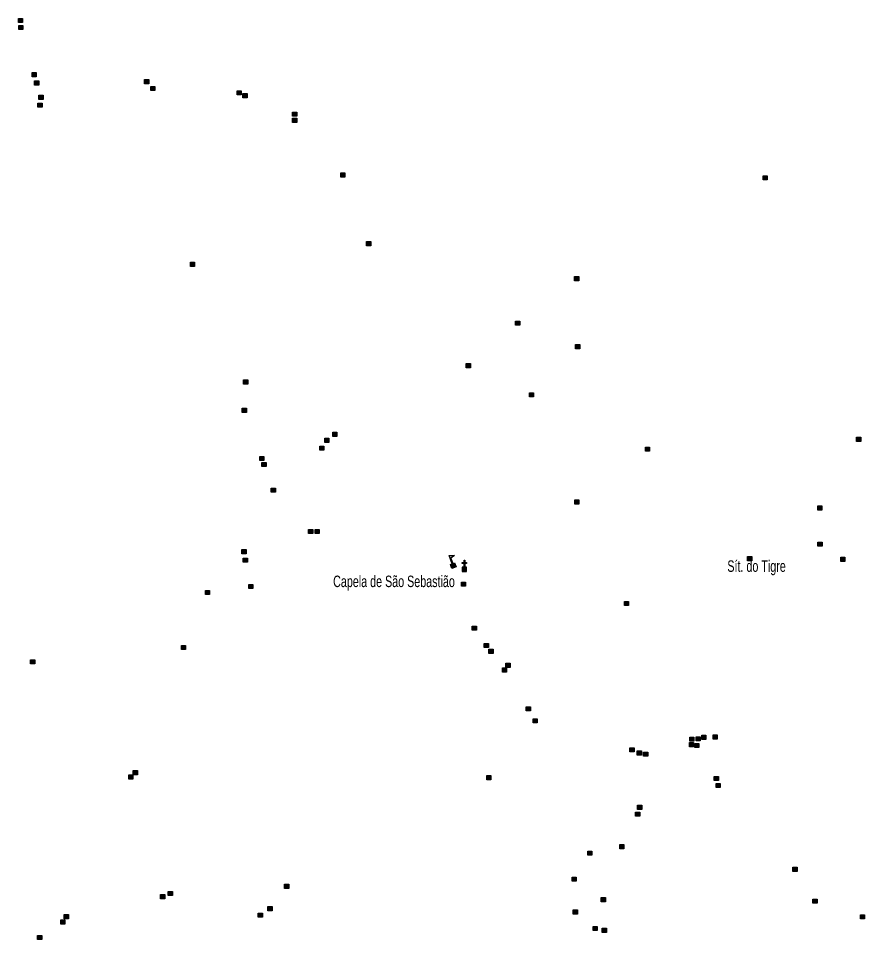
# Model space of a CAD drawing. Extents: x 649.2 to 674.4, y 7040 to 7068.1.
# Drawn here: x 661.96 to 667.86, y 7054.05 to 7060.48 of the extents above; entities that cross this region are included whole.
import ezdxf
from ezdxf.enums import TextEntityAlignment as Align

# ---------------------------------------------------------------- set-up
doc = ezdxf.new("R2010")
doc.units = 0
doc.header["$LTSCALE"] = 0.032
for name, color, linetype, lineweight in [('2', 7, 'Continuous', 25), ('4', 7, 'Continuous', 25), ('6', 7, 'Continuous', 25)]:
    doc.layers.add(name, color=color, linetype=linetype, lineweight=lineweight)
doc.layers.add('61', color=7, linetype='Continuous')

msp = doc.modelspace()

# ---------------------------------------------------------------- hatches: boundary and pattern name
at = {"layer": '2'}
for points in [[(661.9568, 7060.4755), (661.9858, 7060.4755), (661.9858, 7060.4465), (661.9568, 7060.4465)], [(661.9588, 7060.4271), (661.9878, 7060.4271), (661.9878, 7060.3981), (661.9588, 7060.3981)], [(662.0525, 7060.0972), (662.0815, 7060.0972), (662.0815, 7060.0682), (662.0525, 7060.0682)], [(662.0699, 7060.039), (662.0989, 7060.039), (662.0989, 7060.01), (662.0699, 7060.01)], [(662.8376, 7060.0484), (662.8666, 7060.0484), (662.8666, 7060.0194), (662.8376, 7060.0194)], [(662.88, 7060.0005), (662.909, 7060.0005), (662.909, 7059.9715), (662.88, 7059.9715)], [(662.1002, 7059.9388), (662.1292, 7059.9388), (662.1292, 7059.9098), (662.1002, 7059.9098)], [(663.483, 7059.9705), (663.512, 7059.9705), (663.512, 7059.9415), (663.483, 7059.9415)], [(663.523, 7059.9509), (663.552, 7059.9509), (663.552, 7059.9219), (663.523, 7059.9219)], [(662.0932, 7059.884), (662.1222, 7059.884), (662.1222, 7059.855), (662.0932, 7059.855)], [(663.8701, 7059.8221), (663.8991, 7059.8221), (663.8991, 7059.7931), (663.8701, 7059.7931)], [(663.8701, 7059.7786), (663.8991, 7059.7786), (663.8991, 7059.7496), (663.8701, 7059.7496)], [(664.2055, 7059.3977), (664.2345, 7059.3977), (664.2345, 7059.3687), (664.2055, 7059.3687)], [(667.1523, 7059.3776), (667.1813, 7059.3776), (667.1813, 7059.3486), (667.1523, 7059.3486)], [(664.3858, 7058.9185), (664.4148, 7058.9185), (664.4148, 7058.8895), (664.3858, 7058.8895)], [(663.1564, 7058.7742), (663.1854, 7058.7742), (663.1854, 7058.7452), (663.1564, 7058.7452)], [(665.8379, 7058.6738), (665.8669, 7058.6738), (665.8669, 7058.6448), (665.8379, 7058.6448)], [(665.4259, 7058.3627), (665.4549, 7058.3627), (665.4549, 7058.3337), (665.4259, 7058.3337)], [(665.8444, 7058.1992), (665.8734, 7058.1992), (665.8734, 7058.1702), (665.8444, 7058.1702)], [(665.0811, 7058.0661), (665.1101, 7058.0661), (665.1101, 7058.0371), (665.0811, 7058.0371)], [(663.5273, 7057.9528), (663.5563, 7057.9528), (663.5563, 7057.9238), (663.5273, 7057.9238)], [(665.5227, 7057.8632), (665.5517, 7057.8632), (665.5517, 7057.8342), (665.5227, 7057.8342)], [(663.5185, 7057.7551), (663.5475, 7057.7551), (663.5475, 7057.7261), (663.5185, 7057.7261)], [(664.1501, 7057.5873), (664.1791, 7057.5873), (664.1791, 7057.5583), (664.1501, 7057.5583)], [(664.0945, 7057.5457), (664.1235, 7057.5457), (664.1235, 7057.5167), (664.0945, 7057.5167)], [(667.8055, 7057.5522), (667.8345, 7057.5522), (667.8345, 7057.5232), (667.8055, 7057.5232)], [(664.0592, 7057.4908), (664.0882, 7057.4908), (664.0882, 7057.4618), (664.0592, 7057.4618)], [(666.3312, 7057.4838), (666.3602, 7057.4838), (666.3602, 7057.4548), (666.3312, 7057.4548)], [(663.6412, 7057.4184), (663.6702, 7057.4184), (663.6702, 7057.3894), (663.6412, 7057.3894)], [(663.6562, 7057.3771), (663.6852, 7057.3771), (663.6852, 7057.3481), (663.6562, 7057.3481)], [(663.7213, 7057.1973), (663.7503, 7057.1973), (663.7503, 7057.1683), (663.7213, 7057.1683)], [(665.8382, 7057.1146), (665.8672, 7057.1146), (665.8672, 7057.0856), (665.8382, 7057.0856)], [(667.534, 7057.0735), (667.563, 7057.0735), (667.563, 7057.0445), (667.534, 7057.0445)], [(663.9814, 7056.9095), (664.0104, 7056.9095), (664.0104, 7056.8805), (663.9814, 7056.8805)], [(664.0268, 7056.9095), (664.0558, 7056.9095), (664.0558, 7056.8805), (664.0268, 7056.8805)], [(667.5357, 7056.8211), (667.5647, 7056.8211), (667.5647, 7056.7921), (667.5357, 7056.7921)], [(663.5158, 7056.7688), (663.5448, 7056.7688), (663.5448, 7056.7398), (663.5158, 7056.7398)], [(667.0444, 7056.7202), (667.0734, 7056.7202), (667.0734, 7056.6912), (667.0444, 7056.6912)], [(663.5252, 7056.7088), (663.5542, 7056.7088), (663.5542, 7056.6798), (663.5252, 7056.6798)], [(667.6941, 7056.7149), (667.7231, 7056.7149), (667.7231, 7056.6859), (667.6941, 7056.6859)], [(665.0483, 7056.5415), (665.0773, 7056.5415), (665.0773, 7056.5125), (665.0483, 7056.5125)], [(663.2614, 7056.4835), (663.2904, 7056.4835), (663.2904, 7056.4545), (663.2614, 7056.4545)], [(663.5645, 7056.5248), (663.5935, 7056.5248), (663.5935, 7056.4958), (663.5645, 7056.4958)], [(666.1855, 7056.4071), (666.2145, 7056.4071), (666.2145, 7056.3781), (666.1855, 7056.3781)], [(665.123, 7056.2344), (665.152, 7056.2344), (665.152, 7056.2054), (665.123, 7056.2054)], [(663.0939, 7056.0992), (663.1229, 7056.0992), (663.1229, 7056.0702), (663.0939, 7056.0702)], [(665.2069, 7056.1133), (665.2359, 7056.1133), (665.2359, 7056.0843), (665.2069, 7056.0843)], [(665.2399, 7056.0729), (665.2689, 7056.0729), (665.2689, 7056.0439), (665.2399, 7056.0439)], [(662.0413, 7055.9995), (662.0703, 7055.9995), (662.0703, 7055.9705), (662.0413, 7055.9705)], [(665.3578, 7055.9752), (665.3868, 7055.9752), (665.3868, 7055.9462), (665.3578, 7055.9462)], [(665.3333, 7055.9422), (665.3623, 7055.9422), (665.3623, 7055.9132), (665.3333, 7055.9132)], [(665.5003, 7055.6716), (665.5293, 7055.6716), (665.5293, 7055.6426), (665.5003, 7055.6426)], [(665.5483, 7055.5877), (665.5773, 7055.5877), (665.5773, 7055.5587), (665.5483, 7055.5587)], [(666.6409, 7055.4599), (666.6699, 7055.4599), (666.6699, 7055.4309), (666.6409, 7055.4309)], [(666.6848, 7055.4628), (666.7138, 7055.4628), (666.7138, 7055.4338), (666.6848, 7055.4338)], [(666.7244, 7055.4727), (666.7534, 7055.4727), (666.7534, 7055.4437), (666.7244, 7055.4437)], [(666.8036, 7055.4755), (666.8326, 7055.4755), (666.8326, 7055.4465), (666.8036, 7055.4465)], [(666.2236, 7055.385), (666.2526, 7055.385), (666.2526, 7055.356), (666.2236, 7055.356)], [(666.6381, 7055.4217), (666.6671, 7055.4217), (666.6671, 7055.3927), (666.6381, 7055.3927)], [(666.6763, 7055.4161), (666.7053, 7055.4161), (666.7053, 7055.3871), (666.6763, 7055.3871)], [(666.2745, 7055.3637), (666.3035, 7055.3637), (666.3035, 7055.3347), (666.2745, 7055.3347)], [(666.3184, 7055.3553), (666.3474, 7055.3553), (666.3474, 7055.3263), (666.3184, 7055.3263)], [(662.7271, 7055.1964), (662.7561, 7055.1964), (662.7561, 7055.1674), (662.7271, 7055.1674)], [(662.7584, 7055.2264), (662.7874, 7055.2264), (662.7874, 7055.1974), (662.7584, 7055.1974)], [(665.225, 7055.1911), (665.254, 7055.1911), (665.254, 7055.1621), (665.225, 7055.1621)], [(666.8121, 7055.1855), (666.8411, 7055.1855), (666.8411, 7055.1565), (666.8121, 7055.1565)], [(666.8248, 7055.136), (666.8538, 7055.136), (666.8538, 7055.107), (666.8248, 7055.107)], [(666.2773, 7054.9846), (666.3063, 7054.9846), (666.3063, 7054.9556), (666.2773, 7054.9556)], [(666.2632, 7054.9365), (666.2922, 7054.9365), (666.2922, 7054.9075), (666.2632, 7054.9075)], [(665.9296, 7054.6649), (665.9586, 7054.6649), (665.9586, 7054.6359), (665.9296, 7054.6359)], [(666.1522, 7054.7092), (666.1812, 7054.7092), (666.1812, 7054.6802), (666.1522, 7054.6802)], [(667.3612, 7054.5516), (667.3902, 7054.5516), (667.3902, 7054.5226), (667.3612, 7054.5226)], [(665.8203, 7054.4827), (665.8493, 7054.4827), (665.8493, 7054.4537), (665.8203, 7054.4537)], [(663.814, 7054.4331), (663.843, 7054.4331), (663.843, 7054.4041), (663.814, 7054.4041)], [(662.949, 7054.3603), (662.978, 7054.3603), (662.978, 7054.3313), (662.949, 7054.3313)], [(663.0027, 7054.3833), (663.0317, 7054.3833), (663.0317, 7054.3543), (663.0027, 7054.3543)], [(663.6971, 7054.2772), (663.7261, 7054.2772), (663.7261, 7054.2482), (663.6971, 7054.2482)], [(666.0234, 7054.3395), (666.0524, 7054.3395), (666.0524, 7054.3105), (666.0234, 7054.3105)], [(667.5005, 7054.3294), (667.5295, 7054.3294), (667.5295, 7054.3004), (667.5005, 7054.3004)], [(662.2762, 7054.2217), (662.3052, 7054.2217), (662.3052, 7054.1927), (662.2762, 7054.1927)], [(663.6306, 7054.2314), (663.6596, 7054.2314), (663.6596, 7054.2024), (663.6306, 7054.2024)], [(665.8281, 7054.2536), (665.8571, 7054.2536), (665.8571, 7054.2246), (665.8281, 7054.2246)], [(667.8317, 7054.2204), (667.8607, 7054.2204), (667.8607, 7054.1914), (667.8317, 7054.1914)], [(662.2526, 7054.1838), (662.2816, 7054.1838), (662.2816, 7054.1548), (662.2526, 7054.1548)], [(665.9661, 7054.139), (665.9951, 7054.139), (665.9951, 7054.11), (665.9661, 7054.11)], [(666.0299, 7054.126), (666.0589, 7054.126), (666.0589, 7054.097), (666.0299, 7054.097)], [(662.0903, 7054.0758), (662.1193, 7054.0758), (662.1193, 7054.0468), (662.0903, 7054.0468)]]:
    msp.add_hatch(color=256, dxfattribs=at).paths.add_polyline_path(points)
at = {"layer": '4'}
msp.add_hatch(color=256, dxfattribs=at).paths.add_polyline_path([(664.9818, 7056.637), (664.9716, 7056.6652), (664.9999, 7056.6754), (665.0101, 7056.6472)])
at = {"layer": '6'}
for points in [[(665.071, 7056.645), (665.066, 7056.645), (665.066, 7056.6725), (665.0535, 7056.6725), (665.0535, 7056.6775), (665.066, 7056.6775), (665.066, 7056.695), (665.071, 7056.695), (665.071, 7056.6775), (665.0835, 7056.6775), (665.0835, 7056.6725), (665.071, 7056.6725)], [(665.0535, 7056.645), (665.0535, 7056.615), (665.0835, 7056.615), (665.0835, 7056.645)]]:
    msp.add_hatch(color=256, dxfattribs=at).paths.add_polyline_path(points)

# ---------------------------------------------------------------- linework, layer by layer
at = {"layer": '2'}
for points in [[(661.9568, 7060.4755), (661.9858, 7060.4755), (661.9858, 7060.4465), (661.9568, 7060.4465)], [(661.9588, 7060.4271), (661.9878, 7060.4271), (661.9878, 7060.3981), (661.9588, 7060.3981)], [(662.0525, 7060.0972), (662.0815, 7060.0972), (662.0815, 7060.0682), (662.0525, 7060.0682)], [(662.0699, 7060.039), (662.0989, 7060.039), (662.0989, 7060.01), (662.0699, 7060.01)], [(662.8376, 7060.0484), (662.8666, 7060.0484), (662.8666, 7060.0194), (662.8376, 7060.0194)], [(662.88, 7060.0005), (662.909, 7060.0005), (662.909, 7059.9715), (662.88, 7059.9715)], [(662.1002, 7059.9388), (662.1292, 7059.9388), (662.1292, 7059.9098), (662.1002, 7059.9098)], [(663.483, 7059.9705), (663.512, 7059.9705), (663.512, 7059.9415), (663.483, 7059.9415)], [(663.523, 7059.9509), (663.552, 7059.9509), (663.552, 7059.9219), (663.523, 7059.9219)], [(662.0932, 7059.884), (662.1222, 7059.884), (662.1222, 7059.855), (662.0932, 7059.855)], [(663.8701, 7059.8221), (663.8991, 7059.8221), (663.8991, 7059.7931), (663.8701, 7059.7931)], [(663.8701, 7059.7786), (663.8991, 7059.7786), (663.8991, 7059.7496), (663.8701, 7059.7496)], [(664.2055, 7059.3977), (664.2345, 7059.3977), (664.2345, 7059.3687), (664.2055, 7059.3687)], [(667.1523, 7059.3776), (667.1813, 7059.3776), (667.1813, 7059.3486), (667.1523, 7059.3486)], [(664.3858, 7058.9185), (664.4148, 7058.9185), (664.4148, 7058.8895), (664.3858, 7058.8895)], [(663.1564, 7058.7742), (663.1854, 7058.7742), (663.1854, 7058.7452), (663.1564, 7058.7452)], [(665.8379, 7058.6738), (665.8669, 7058.6738), (665.8669, 7058.6448), (665.8379, 7058.6448)], [(665.4259, 7058.3627), (665.4549, 7058.3627), (665.4549, 7058.3337), (665.4259, 7058.3337)], [(665.8444, 7058.1992), (665.8734, 7058.1992), (665.8734, 7058.1702), (665.8444, 7058.1702)], [(665.0811, 7058.0661), (665.1101, 7058.0661), (665.1101, 7058.0371), (665.0811, 7058.0371)], [(663.5273, 7057.9528), (663.5563, 7057.9528), (663.5563, 7057.9238), (663.5273, 7057.9238)], [(665.5227, 7057.8632), (665.5517, 7057.8632), (665.5517, 7057.8342), (665.5227, 7057.8342)], [(663.5185, 7057.7551), (663.5475, 7057.7551), (663.5475, 7057.7261), (663.5185, 7057.7261)], [(664.1501, 7057.5873), (664.1791, 7057.5873), (664.1791, 7057.5583), (664.1501, 7057.5583)], [(664.0945, 7057.5457), (664.1235, 7057.5457), (664.1235, 7057.5167), (664.0945, 7057.5167)], [(667.8055, 7057.5522), (667.8345, 7057.5522), (667.8345, 7057.5232), (667.8055, 7057.5232)], [(664.0592, 7057.4908), (664.0882, 7057.4908), (664.0882, 7057.4618), (664.0592, 7057.4618)], [(666.3312, 7057.4838), (666.3602, 7057.4838), (666.3602, 7057.4548), (666.3312, 7057.4548)], [(663.6412, 7057.4184), (663.6702, 7057.4184), (663.6702, 7057.3894), (663.6412, 7057.3894)], [(663.6562, 7057.3771), (663.6852, 7057.3771), (663.6852, 7057.3481), (663.6562, 7057.3481)], [(663.7213, 7057.1973), (663.7503, 7057.1973), (663.7503, 7057.1683), (663.7213, 7057.1683)], [(665.8382, 7057.1146), (665.8672, 7057.1146), (665.8672, 7057.0856), (665.8382, 7057.0856)], [(667.534, 7057.0735), (667.563, 7057.0735), (667.563, 7057.0445), (667.534, 7057.0445)], [(663.9814, 7056.9095), (664.0104, 7056.9095), (664.0104, 7056.8805), (663.9814, 7056.8805)], [(664.0268, 7056.9095), (664.0558, 7056.9095), (664.0558, 7056.8805), (664.0268, 7056.8805)], [(667.5357, 7056.8211), (667.5647, 7056.8211), (667.5647, 7056.7921), (667.5357, 7056.7921)], [(663.5158, 7056.7688), (663.5448, 7056.7688), (663.5448, 7056.7398), (663.5158, 7056.7398)], [(667.0444, 7056.7202), (667.0734, 7056.7202), (667.0734, 7056.6912), (667.0444, 7056.6912)], [(663.5252, 7056.7088), (663.5542, 7056.7088), (663.5542, 7056.6798), (663.5252, 7056.6798)], [(667.6941, 7056.7149), (667.7231, 7056.7149), (667.7231, 7056.6859), (667.6941, 7056.6859)], [(665.0483, 7056.5415), (665.0773, 7056.5415), (665.0773, 7056.5125), (665.0483, 7056.5125)], [(663.2614, 7056.4835), (663.2904, 7056.4835), (663.2904, 7056.4545), (663.2614, 7056.4545)], [(663.5645, 7056.5248), (663.5935, 7056.5248), (663.5935, 7056.4958), (663.5645, 7056.4958)], [(666.1855, 7056.4071), (666.2145, 7056.4071), (666.2145, 7056.3781), (666.1855, 7056.3781)], [(665.123, 7056.2344), (665.152, 7056.2344), (665.152, 7056.2054), (665.123, 7056.2054)], [(663.0939, 7056.0992), (663.1229, 7056.0992), (663.1229, 7056.0702), (663.0939, 7056.0702)], [(665.2069, 7056.1133), (665.2359, 7056.1133), (665.2359, 7056.0843), (665.2069, 7056.0843)], [(665.2399, 7056.0729), (665.2689, 7056.0729), (665.2689, 7056.0439), (665.2399, 7056.0439)], [(662.0413, 7055.9995), (662.0703, 7055.9995), (662.0703, 7055.9705), (662.0413, 7055.9705)], [(665.3578, 7055.9752), (665.3868, 7055.9752), (665.3868, 7055.9462), (665.3578, 7055.9462)], [(665.3333, 7055.9422), (665.3623, 7055.9422), (665.3623, 7055.9132), (665.3333, 7055.9132)], [(665.5003, 7055.6716), (665.5293, 7055.6716), (665.5293, 7055.6426), (665.5003, 7055.6426)], [(665.5483, 7055.5877), (665.5773, 7055.5877), (665.5773, 7055.5587), (665.5483, 7055.5587)], [(666.6409, 7055.4599), (666.6699, 7055.4599), (666.6699, 7055.4309), (666.6409, 7055.4309)], [(666.6848, 7055.4628), (666.7138, 7055.4628), (666.7138, 7055.4338), (666.6848, 7055.4338)], [(666.7244, 7055.4727), (666.7534, 7055.4727), (666.7534, 7055.4437), (666.7244, 7055.4437)], [(666.8036, 7055.4755), (666.8326, 7055.4755), (666.8326, 7055.4465), (666.8036, 7055.4465)], [(666.2236, 7055.385), (666.2526, 7055.385), (666.2526, 7055.356), (666.2236, 7055.356)], [(666.6381, 7055.4217), (666.6671, 7055.4217), (666.6671, 7055.3927), (666.6381, 7055.3927)], [(666.6763, 7055.4161), (666.7053, 7055.4161), (666.7053, 7055.3871), (666.6763, 7055.3871)], [(666.2745, 7055.3637), (666.3035, 7055.3637), (666.3035, 7055.3347), (666.2745, 7055.3347)], [(666.3184, 7055.3553), (666.3474, 7055.3553), (666.3474, 7055.3263), (666.3184, 7055.3263)], [(662.7271, 7055.1964), (662.7561, 7055.1964), (662.7561, 7055.1674), (662.7271, 7055.1674)], [(662.7584, 7055.2264), (662.7874, 7055.2264), (662.7874, 7055.1974), (662.7584, 7055.1974)], [(665.225, 7055.1911), (665.254, 7055.1911), (665.254, 7055.1621), (665.225, 7055.1621)], [(666.8121, 7055.1855), (666.8411, 7055.1855), (666.8411, 7055.1565), (666.8121, 7055.1565)], [(666.8248, 7055.136), (666.8538, 7055.136), (666.8538, 7055.107), (666.8248, 7055.107)], [(666.2773, 7054.9846), (666.3063, 7054.9846), (666.3063, 7054.9556), (666.2773, 7054.9556)], [(666.2632, 7054.9365), (666.2922, 7054.9365), (666.2922, 7054.9075), (666.2632, 7054.9075)], [(665.9296, 7054.6649), (665.9586, 7054.6649), (665.9586, 7054.6359), (665.9296, 7054.6359)], [(666.1522, 7054.7092), (666.1812, 7054.7092), (666.1812, 7054.6802), (666.1522, 7054.6802)], [(667.3612, 7054.5516), (667.3902, 7054.5516), (667.3902, 7054.5226), (667.3612, 7054.5226)], [(665.8203, 7054.4827), (665.8493, 7054.4827), (665.8493, 7054.4537), (665.8203, 7054.4537)], [(663.814, 7054.4331), (663.843, 7054.4331), (663.843, 7054.4041), (663.814, 7054.4041)], [(662.949, 7054.3603), (662.978, 7054.3603), (662.978, 7054.3313), (662.949, 7054.3313)], [(663.0027, 7054.3833), (663.0317, 7054.3833), (663.0317, 7054.3543), (663.0027, 7054.3543)], [(663.6971, 7054.2772), (663.7261, 7054.2772), (663.7261, 7054.2482), (663.6971, 7054.2482)], [(666.0234, 7054.3395), (666.0524, 7054.3395), (666.0524, 7054.3105), (666.0234, 7054.3105)], [(667.5005, 7054.3294), (667.5295, 7054.3294), (667.5295, 7054.3004), (667.5005, 7054.3004)], [(662.2762, 7054.2217), (662.3052, 7054.2217), (662.3052, 7054.1927), (662.2762, 7054.1927)], [(663.6306, 7054.2314), (663.6596, 7054.2314), (663.6596, 7054.2024), (663.6306, 7054.2024)], [(665.8281, 7054.2536), (665.8571, 7054.2536), (665.8571, 7054.2246), (665.8281, 7054.2246)], [(667.8317, 7054.2204), (667.8607, 7054.2204), (667.8607, 7054.1914), (667.8317, 7054.1914)], [(662.2526, 7054.1838), (662.2816, 7054.1838), (662.2816, 7054.1548), (662.2526, 7054.1548)], [(665.9661, 7054.139), (665.9951, 7054.139), (665.9951, 7054.11), (665.9661, 7054.11)], [(666.0299, 7054.126), (666.0589, 7054.126), (666.0589, 7054.097), (666.0299, 7054.097)], [(662.0903, 7054.0758), (662.1193, 7054.0758), (662.1193, 7054.0468), (662.0903, 7054.0468)]]:
    msp.add_lwpolyline(points, close=True, dxfattribs=at)
at = {"layer": '4'}
msp.add_line((664.9834, 7056.6694), (664.9881, 7056.6711), dxfattribs=at)
for points in [[(664.9834, 7056.6694), (664.9621, 7056.7282), (664.9993, 7056.7284), (664.9747, 7056.7083), (664.9881, 7056.6711)], [(664.9818, 7056.637), (664.9716, 7056.6652), (664.9999, 7056.6754), (665.0101, 7056.6472)]]:
    msp.add_lwpolyline(points, close=True, dxfattribs=at)
at = {"layer": '6'}
for points in [[(665.071, 7056.645), (665.066, 7056.645), (665.066, 7056.6725), (665.0535, 7056.6725), (665.0535, 7056.6775), (665.066, 7056.6775), (665.066, 7056.695), (665.071, 7056.695), (665.071, 7056.6775), (665.0835, 7056.6775), (665.0835, 7056.6725), (665.071, 7056.6725)], [(665.0535, 7056.645), (665.0535, 7056.615), (665.0835, 7056.615), (665.0835, 7056.645)]]:
    msp.add_lwpolyline(points, close=True, dxfattribs=at)

# ---------------------------------------------------------------- texts
at = {"layer": '61', "width": 0.7}
msp.add_text('Sít. do Tigre', height=0.08, dxfattribs=at).set_placement((666.9031, 7056.6131))
msp.add_text('Capela de São Sebastião', height=0.08, dxfattribs=at).set_placement((665.002, 7056.5068), align=Align.RIGHT)

doc.saveas('drawing.dxf')
